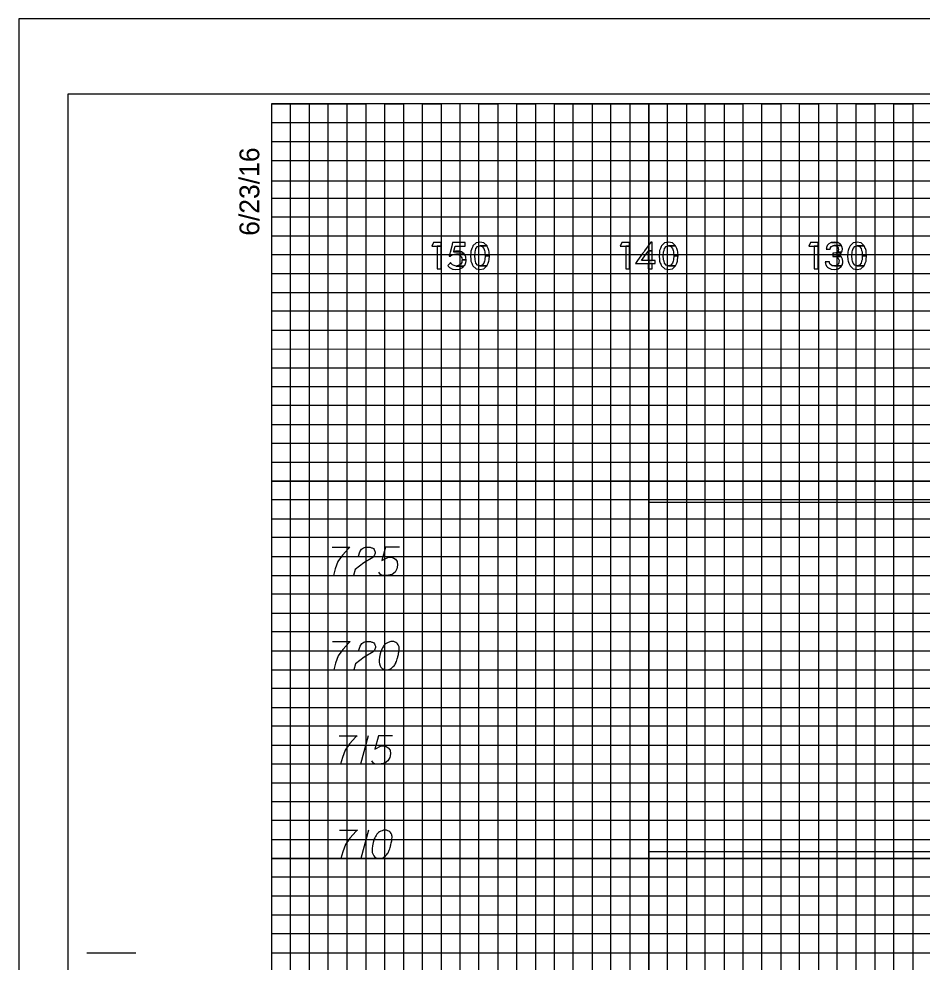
# Model space of a CAD drawing. Extents: x -13 to 323, y -5 to 1431.
# Drawn here: x -13.4 to 34.5, y 824.5 to 874.5 of the extents above; entities that cross this region are included whole.
import ezdxf

# ---------------------------------------------------------------- set-up
doc = ezdxf.new("R2010")
doc.units = 0
for name, color, linetype in [('Prop XS Elevation Labels', 7, 'Continuous'), ('Prop XS Offset Labels', 7, 'Continuous'), ('Scratch_Level_3', 7, 'Continuous'), ('Sheet Cross Section CELL', 7, 'Continuous'), ('Sheet Cross Section Grid Major CELL', 7, 'Continuous'), ('Sheet Cross Section Grid Middle CELL', 7, 'Continuous'), ('Sheet Cross Section Grid Minor 1 CELL', 7, 'Continuous'), ('Sheet Cross Section Grid Minor 2 CELL', 7, 'Continuous'), ('Sheet Cutting Line CELL', 7, 'Continuous'), ('Sheet DOT Grid CELL', 7, 'Continuous'), ('Sheet Plot Border Inside CELL', 7, 'Continuous'), ('Sheet Plot Border Outside CELL', 7, 'Continuous')]:
    doc.layers.add(name, color=color, linetype=linetype)

msp = doc.modelspace()

# ---------------------------------------------------------------- linework, layer by layer
at = {"layer": 'Prop XS Elevation Labels'}
for p, q in [((5.124, 836.5), (4.723, 835)), ((5.142, 831.5), (4.74, 830))]:
    msp.add_line(p, q, dxfattribs=at)
for points in [[(3.211, 846.5), (4.155, 846.5), (4.096, 846.441), (3.754, 846.075), (3.518, 845.744), (3.376, 845.354), (3.281, 845)], [(4.616, 846.028), (4.675, 846.252), (4.77, 846.394), (4.876, 846.453), (4.982, 846.488), (5.065, 846.5), (5.124, 846.5), (5.23, 846.488), (5.301, 846.465), (5.337, 846.453), (5.408, 846.417), (5.443, 846.37), (5.467, 846.323), (5.478, 846.287), (5.49, 846.24), (5.49, 846.181), (5.478, 846.122), (5.467, 846.087), (5.443, 846.039), (5.408, 845.992), (5.372, 845.957), (4.888, 845.661), (4.427, 845.319), (4.345, 845), (5.419, 845)], [(6.789, 846.5), (6.045, 846.5), (5.856, 845.791), (6.199, 845.969), (6.4, 845.969), (6.565, 845.862), (6.66, 845.744), (6.683, 845.543), (6.648, 845.342), (6.553, 845.177), (6.388, 845.047), (6.104, 845), (5.892, 845), (5.785, 845.047), (5.691, 845.177)], [(3.228, 841.5), (4.173, 841.5), (4.114, 841.441), (3.772, 841.075), (3.535, 840.744), (3.394, 840.354), (3.299, 840)], [(4.634, 841.028), (4.693, 841.252), (4.787, 841.394), (4.894, 841.453), (5, 841.488), (5.083, 841.5), (5.142, 841.5), (5.248, 841.488), (5.319, 841.465), (5.354, 841.453), (5.425, 841.417), (5.461, 841.37), (5.484, 841.323), (5.496, 841.287), (5.508, 841.24), (5.508, 841.181), (5.496, 841.122), (5.484, 841.087), (5.461, 841.039), (5.425, 840.992), (5.39, 840.957), (4.906, 840.661), (4.445, 840.319), (4.362, 840), (5.437, 840)], [(6.417, 841.5), (6.394, 841.5), (6.323, 841.488), (6.276, 841.476), (6.24, 841.465), (6.181, 841.441), (6.11, 841.406), (6.051, 841.37), (5.992, 841.323), (5.957, 841.276), (5.921, 841.217), (5.886, 841.158), (5.85, 841.087), (5.827, 841.039), (5.803, 840.969), (5.768, 840.85), (5.732, 840.673), (5.709, 840.531), (5.709, 840.402), (5.721, 840.307), (5.768, 840.201), (5.803, 840.142), (5.862, 840.071), (5.933, 840.024), (5.968, 840.012), (6.039, 840), (6.098, 840), (6.193, 840.012), (6.276, 840.035), (6.335, 840.071), (6.417, 840.13), (6.453, 840.165), (6.5, 840.213), (6.535, 840.26), (6.559, 840.295), (6.583, 840.354), (6.594, 840.378), (6.618, 840.437), (6.642, 840.508), (6.665, 840.579), (6.677, 840.626), (6.689, 840.661), (6.701, 840.709), (6.724, 840.815), (6.736, 840.874), (6.748, 840.933), (6.76, 841.016), (6.772, 841.122), (6.772, 841.158), (6.76, 841.205), (6.748, 841.252), (6.713, 841.323), (6.677, 841.37), (6.642, 841.406), (6.594, 841.441), (6.547, 841.465), (6.512, 841.476), (6.476, 841.488), (6.417, 841.5)], [(3.589, 836.5), (4.533, 836.5), (4.474, 836.441), (4.132, 836.075), (3.896, 835.744), (3.754, 835.354), (3.659, 835)], [(6.411, 836.5), (5.667, 836.5), (5.478, 835.791), (5.821, 835.969), (6.022, 835.969), (6.187, 835.862), (6.282, 835.744), (6.305, 835.543), (6.27, 835.342), (6.175, 835.177), (6.01, 835.047), (5.726, 835), (5.514, 835), (5.408, 835.047), (5.313, 835.177)], [(3.606, 831.5), (4.551, 831.5), (4.492, 831.441), (4.149, 831.075), (3.913, 830.744), (3.772, 830.354), (3.677, 830)], [(6.039, 831.5), (6.016, 831.5), (5.945, 831.488), (5.898, 831.476), (5.862, 831.465), (5.803, 831.441), (5.732, 831.406), (5.673, 831.37), (5.614, 831.323), (5.579, 831.276), (5.543, 831.217), (5.508, 831.158), (5.472, 831.087), (5.449, 831.039), (5.425, 830.969), (5.39, 830.85), (5.354, 830.673), (5.331, 830.531), (5.331, 830.402), (5.343, 830.307), (5.39, 830.201), (5.425, 830.142), (5.484, 830.071), (5.555, 830.024), (5.591, 830.012), (5.661, 830), (5.72, 830), (5.815, 830.012), (5.898, 830.035), (5.957, 830.071), (6.039, 830.13), (6.075, 830.165), (6.122, 830.213), (6.157, 830.26), (6.181, 830.295), (6.205, 830.354), (6.217, 830.378), (6.24, 830.437), (6.264, 830.508), (6.287, 830.579), (6.299, 830.626), (6.311, 830.661), (6.323, 830.709), (6.347, 830.815), (6.358, 830.874), (6.37, 830.933), (6.382, 831.016), (6.394, 831.122), (6.394, 831.158), (6.382, 831.205), (6.37, 831.252), (6.335, 831.323), (6.299, 831.37), (6.264, 831.406), (6.217, 831.441), (6.169, 831.465), (6.134, 831.476), (6.098, 831.488), (6.039, 831.5)]]:
    msp.add_lwpolyline(points, dxfattribs=at)
at = {"layer": 'Prop XS Offset Labels'}
for points in [[(8.581, 862.641), (8.492, 862.459), (8.99, 862.459), (8.99, 862.641)], [(9.427, 861.94), (9.424, 861.928), (9.495, 861.928), (9.508, 861.94), (9.524, 861.954), (9.595, 861.997), (9.627, 862.007), (9.697, 862.029), (9.811, 862.035), (10.219, 862.035), (10.211, 862.05), (10.076, 862.145), (9.655, 862.145), (9.658, 862.158), (9.658, 862.158), (9.663, 862.178), (9.738, 862.456), (10.263, 862.456), (10.263, 862.641), (9.6, 862.641), (9.554, 862.456), (9.486, 862.178), (9.481, 862.158), (9.478, 862.145), (9.454, 862.05), (9.451, 862.035), (9.449, 862.029), (9.444, 862.007), (9.441, 861.997), (9.431, 861.954)], [(10.851, 861.255), (11.051, 861.214), (11.245, 861.255), (11.256, 861.257), (11.422, 861.409), (11.047, 861.409), (11.038, 861.411), (11.033, 861.413), (10.928, 861.442), (10.841, 861.555), (10.841, 861.556), (10.841, 861.556), (10.813, 861.657), (10.813, 861.659), (10.793, 861.732), (10.792, 861.736), (10.774, 861.939), (10.774, 861.941), (10.774, 861.943), (10.792, 862.145), (10.812, 862.222), (10.813, 862.224), (10.839, 862.322), (10.84, 862.325), (10.928, 862.44), (11.041, 862.469), (11.045, 862.47), (11.055, 862.473), (11.425, 862.473), (11.262, 862.622), (11.254, 862.624), (11.053, 862.668), (11.053, 862.668), (10.845, 862.624), (10.843, 862.622), (10.681, 862.473), (10.678, 862.47), (10.678, 862.469), (10.665, 862.44), (10.618, 862.325), (10.617, 862.322), (10.577, 862.224), (10.576, 862.222), (10.568, 862.145), (10.547, 861.943), (10.547, 861.941), (10.547, 861.939), (10.567, 861.736), (10.568, 861.732), (10.575, 861.659), (10.575, 861.657), (10.616, 861.556), (10.617, 861.555), (10.663, 861.442), (10.675, 861.413), (10.676, 861.411), (10.679, 861.409), (10.848, 861.257)], [(18.581, 862.641), (18.492, 862.459), (18.99, 862.459), (18.99, 862.641)], [(19.411, 861.693), (19.297, 861.534), (20.35, 861.534), (20.35, 861.693), (19.618, 861.693), (19.878, 862.059), (19.935, 862.139), (19.977, 862.199), (20.179, 862.199), (20.179, 862.668), (20.114, 862.668), (19.775, 862.199), (19.733, 862.139), (19.675, 862.059)], [(20.851, 861.255), (21.051, 861.214), (21.245, 861.255), (21.256, 861.257), (21.422, 861.409), (21.047, 861.409), (21.038, 861.411), (21.033, 861.413), (20.928, 861.442), (20.841, 861.555), (20.841, 861.556), (20.841, 861.556), (20.813, 861.657), (20.813, 861.659), (20.793, 861.732), (20.792, 861.736), (20.774, 861.939), (20.774, 861.941), (20.774, 861.943), (20.792, 862.145), (20.812, 862.222), (20.813, 862.224), (20.839, 862.322), (20.84, 862.325), (20.928, 862.44), (21.041, 862.469), (21.045, 862.47), (21.055, 862.473), (21.425, 862.473), (21.262, 862.622), (21.254, 862.624), (21.053, 862.668), (21.053, 862.668), (20.845, 862.624), (20.843, 862.622), (20.681, 862.473), (20.678, 862.47), (20.678, 862.469), (20.665, 862.44), (20.618, 862.325), (20.617, 862.322), (20.577, 862.224), (20.576, 862.222), (20.568, 862.145), (20.547, 861.943), (20.547, 861.941), (20.547, 861.939), (20.567, 861.736), (20.567, 861.732), (20.575, 861.659), (20.575, 861.657), (20.616, 861.556), (20.617, 861.555), (20.663, 861.442), (20.675, 861.413), (20.676, 861.411), (20.679, 861.409), (20.848, 861.257)], [(28.581, 862.641), (28.492, 862.459), (28.99, 862.459), (28.99, 862.641)], [(29.42, 862.315), (29.418, 862.297), (29.626, 862.297), (29.627, 862.315), (29.639, 862.365), (29.64, 862.372), (29.641, 862.373), (29.683, 862.433), (29.688, 862.436), (29.696, 862.44), (29.748, 862.47), (29.785, 862.476), (29.795, 862.478), (29.835, 862.485), (30.217, 862.485), (30.165, 862.561), (30.129, 862.582), (30.128, 862.582), (30.023, 862.644), (29.982, 862.65), (29.69, 862.65), (29.678, 862.644), (29.553, 862.582), (29.536, 862.561), (29.471, 862.485), (29.466, 862.478), (29.465, 862.476), (29.463, 862.47), (29.452, 862.44), (29.45, 862.436), (29.449, 862.433), (29.428, 862.373), (29.427, 862.372), (29.425, 862.365)], [(29.853, 862.668), (29.69, 862.65), (29.982, 862.65)], [(30.851, 861.255), (31.051, 861.214), (31.245, 861.255), (31.256, 861.257), (31.422, 861.409), (31.047, 861.409), (31.038, 861.411), (31.033, 861.413), (30.928, 861.442), (30.841, 861.555), (30.841, 861.556), (30.841, 861.556), (30.813, 861.657), (30.813, 861.659), (30.793, 861.732), (30.792, 861.736), (30.774, 861.939), (30.774, 861.941), (30.774, 861.943), (30.792, 862.145), (30.812, 862.222), (30.813, 862.224), (30.839, 862.322), (30.84, 862.325), (30.928, 862.44), (31.041, 862.469), (31.045, 862.47), (31.055, 862.473), (31.425, 862.473), (31.262, 862.622), (31.254, 862.624), (31.053, 862.668), (31.053, 862.668), (30.845, 862.624), (30.843, 862.622), (30.681, 862.473), (30.678, 862.47), (30.678, 862.469), (30.665, 862.44), (30.618, 862.325), (30.617, 862.322), (30.577, 862.224), (30.576, 862.222), (30.568, 862.145), (30.547, 861.943), (30.547, 861.941), (30.547, 861.939), (30.567, 861.736), (30.567, 861.732), (30.575, 861.659), (30.575, 861.657), (30.616, 861.556), (30.617, 861.555), (30.663, 861.442), (30.675, 861.413), (30.676, 861.411), (30.679, 861.409), (30.848, 861.257)], [(8.781, 862.459), (8.781, 861.25), (8.99, 861.25), (8.99, 862.459)], [(9.692, 862.158), (9.655, 862.145), (10.076, 862.145), (10.058, 862.158), (9.961, 862.178), (9.75, 862.178)], [(9.888, 862.192), (9.75, 862.178), (9.96, 862.178), (9.888, 862.192)], [(10.083, 861.841), (10.105, 861.721), (10.318, 861.721), (10.307, 861.841), (10.307, 861.841), (10.303, 861.881), (10.284, 861.916), (10.278, 861.928), (10.271, 861.94), (10.263, 861.954), (10.24, 861.997), (10.235, 862.007), (10.223, 862.029), (10.219, 862.035), (9.811, 862.035), (9.838, 862.029), (9.928, 862.007), (9.943, 861.997), (10.003, 861.954), (10.024, 861.94), (10.031, 861.928), (10.038, 861.916), (10.059, 861.881)], [(11.312, 862.145), (11.328, 861.943), (11.555, 861.943), (11.536, 862.145), (11.528, 862.222), (11.527, 862.224), (11.527, 862.224), (11.488, 862.322), (11.488, 862.322), (11.487, 862.325), (11.441, 862.44), (11.44, 862.44), (11.429, 862.469), (11.428, 862.47), (11.425, 862.473), (11.055, 862.473), (11.065, 862.47), (11.068, 862.469), (11.175, 862.44), (11.262, 862.325), (11.265, 862.322), (11.291, 862.224), (11.291, 862.222)], [(18.781, 862.459), (18.781, 861.25), (18.99, 861.25), (18.99, 862.459)], [(19.97, 862.059), (19.97, 861.693), (20.179, 861.693), (20.179, 862.059), (20.179, 862.139), (20.179, 862.199), (19.977, 862.199), (19.973, 862.139)], [(21.312, 862.145), (21.328, 861.943), (21.555, 861.943), (21.536, 862.145), (21.528, 862.222), (21.527, 862.224), (21.527, 862.224), (21.488, 862.322), (21.488, 862.322), (21.487, 862.325), (21.441, 862.44), (21.44, 862.44), (21.429, 862.469), (21.428, 862.47), (21.425, 862.473), (21.055, 862.473), (21.065, 862.47), (21.068, 862.469), (21.175, 862.44), (21.262, 862.325), (21.265, 862.322), (21.291, 862.224), (21.291, 862.222)], [(28.781, 862.459), (28.781, 861.25), (28.99, 861.25), (28.99, 862.459)], [(29.765, 861.956), (29.765, 861.9), (30.194, 861.9), (30.119, 861.956), (30.029, 861.983), (30.095, 862), (30.181, 862.053), (30.2, 862.084), (30.201, 862.085), (30.207, 862.095), (29.915, 862.095), (29.83, 862.085), (29.765, 862.084), (29.765, 862.053), (29.765, 862), (29.765, 861.983)], [(30.007, 862.155), (29.988, 862.131), (30.23, 862.131), (30.246, 862.155), (30.254, 862.201), (30.271, 862.289), (30.272, 862.295), (30.272, 862.297), (30.269, 862.315), (30.26, 862.365), (30.259, 862.372), (30.259, 862.373), (30.259, 862.373), (30.249, 862.433), (30.248, 862.436), (30.248, 862.44), (30.227, 862.47), (30.223, 862.476), (30.222, 862.478), (30.217, 862.485), (29.835, 862.485), (29.901, 862.478), (29.919, 862.476), (29.931, 862.47), (29.986, 862.44), (29.995, 862.436), (29.997, 862.433), (30.04, 862.373), (30.04, 862.372), (30.042, 862.365), (30.051, 862.315), (30.054, 862.297), (30.055, 862.295), (30.056, 862.289), (30.041, 862.201)], [(29.988, 862.131), (29.915, 862.095), (30.207, 862.095), (30.23, 862.131)], [(31.312, 862.145), (31.328, 861.943), (31.555, 861.943), (31.536, 862.145), (31.528, 862.222), (31.527, 862.224), (31.527, 862.224), (31.488, 862.322), (31.488, 862.322), (31.487, 862.325), (31.441, 862.44), (31.44, 862.44), (31.429, 862.469), (31.428, 862.47), (31.425, 862.473), (31.055, 862.473), (31.065, 862.47), (31.068, 862.469), (31.175, 862.44), (31.262, 862.325), (31.265, 862.322), (31.291, 862.224), (31.291, 862.222)], [(9.626, 861.233), (9.762, 861.214), (9.959, 861.233), (9.968, 861.237), (10.091, 861.297), (10.091, 861.297), (10.141, 861.321), (10.185, 861.375), (10.204, 861.399), (9.793, 861.399), (9.683, 861.418), (9.682, 861.419), (9.679, 861.42), (9.596, 861.466), (9.586, 861.477), (9.58, 861.483), (9.58, 861.483), (9.529, 861.535), (9.497, 861.585), (9.497, 861.585), (9.451, 861.535), (9.404, 861.483), (9.399, 861.477), (9.39, 861.466), (9.348, 861.42), (9.347, 861.419), (9.348, 861.418), (9.363, 861.399), (9.382, 861.375), (9.445, 861.321), (9.474, 861.297), (9.598, 861.237)], [(9.424, 861.928), (9.482, 861.916), (9.495, 861.928)], [(9.9, 861.418), (9.793, 861.399), (10.204, 861.399), (10.22, 861.418), (10.221, 861.419), (10.222, 861.42), (10.222, 861.42), (10.259, 861.466), (10.268, 861.477), (10.27, 861.483), (10.284, 861.535), (10.299, 861.59), (10.322, 861.674), (10.318, 861.721), (10.105, 861.721), (10.097, 861.674), (10.082, 861.59), (10.047, 861.535), (10.014, 861.483), (10.004, 861.477), (9.987, 861.466), (9.913, 861.42), (9.905, 861.419)], [(11.058, 861.411), (11.047, 861.409), (11.422, 861.409), (11.425, 861.411), (11.426, 861.413), (11.438, 861.442), (11.485, 861.555), (11.485, 861.556), (11.527, 861.657), (11.528, 861.659), (11.535, 861.732), (11.535, 861.736), (11.555, 861.939), (11.556, 861.941), (11.555, 861.943), (11.328, 861.943), (11.328, 861.941), (11.328, 861.939), (11.312, 861.736), (11.312, 861.732), (11.292, 861.659), (11.291, 861.657), (11.264, 861.556), (11.263, 861.555), (11.175, 861.442), (11.063, 861.413)], [(19.97, 861.534), (19.97, 861.25), (20.179, 861.25), (20.179, 861.534)], [(21.058, 861.411), (21.047, 861.409), (21.422, 861.409), (21.425, 861.411), (21.426, 861.413), (21.438, 861.442), (21.485, 861.555), (21.485, 861.556), (21.527, 861.657), (21.528, 861.659), (21.535, 861.732), (21.535, 861.736), (21.555, 861.939), (21.556, 861.941), (21.555, 861.943), (21.328, 861.943), (21.328, 861.941), (21.328, 861.939), (21.312, 861.736), (21.312, 861.732), (21.292, 861.659), (21.291, 861.657), (21.264, 861.556), (21.263, 861.555), (21.175, 861.442), (21.063, 861.413)], [(29.677, 861.229), (29.854, 861.214), (29.936, 861.229), (30.042, 861.248), (30.123, 861.297), (30.187, 861.336), (30.228, 861.399), (30.229, 861.401), (29.849, 861.401), (29.72, 861.416), (29.711, 861.423), (29.639, 861.471), (29.628, 861.479), (29.626, 861.482), (29.608, 861.516), (29.584, 861.562), (29.584, 861.567), (29.58, 861.62), (29.58, 861.625), (29.361, 861.625), (29.362, 861.62), (29.369, 861.567), (29.37, 861.562), (29.377, 861.516), (29.391, 861.482), (29.392, 861.479), (29.395, 861.471), (29.415, 861.423), (29.418, 861.416), (29.425, 861.401), (29.426, 861.399), (29.49, 861.336), (29.53, 861.297), (29.635, 861.248)], [(29.925, 861.416), (29.849, 861.401), (30.229, 861.401), (30.239, 861.416), (30.243, 861.423), (30.243, 861.423), (30.275, 861.471), (30.277, 861.479), (30.277, 861.482), (30.283, 861.516), (30.292, 861.562), (30.293, 861.567), (30.303, 861.62), (30.297, 861.662), (30.285, 861.751), (30.283, 861.763), (30.25, 861.826), (30.223, 861.877), (30.222, 861.88), (30.197, 861.898), (30.194, 861.9), (29.81, 861.9), (29.878, 861.898), (29.951, 861.88), (29.963, 861.877), (30.033, 861.826), (30.07, 861.763), (30.077, 861.751), (30.092, 861.662), (30.088, 861.62), (30.083, 861.567), (30.08, 861.562), (30.057, 861.516), (30.039, 861.482), (30.035, 861.479), (30.025, 861.471), (29.957, 861.423)], [(31.058, 861.411), (31.047, 861.409), (31.422, 861.409), (31.425, 861.411), (31.426, 861.413), (31.438, 861.442), (31.485, 861.555), (31.485, 861.556), (31.527, 861.657), (31.528, 861.659), (31.535, 861.732), (31.535, 861.736), (31.555, 861.939), (31.556, 861.941), (31.555, 861.943), (31.328, 861.943), (31.328, 861.941), (31.328, 861.939), (31.312, 861.736), (31.312, 861.732), (31.292, 861.659), (31.291, 861.657), (31.264, 861.556), (31.263, 861.555), (31.175, 861.442), (31.063, 861.413)]]:
    msp.add_lwpolyline(points, close=True, dxfattribs=at)
at = {"layer": 'Scratch_Level_3'}
msp.add_lwpolyline([(20, 848.886), (300, 848.886), (300, 830.355), (20, 830.355)], close=True, dxfattribs=at)
at = {"layer": 'Sheet Cross Section CELL'}
for p, q in [((-9.8, 825), (-7.3, 825)), ((-9.7, 825), (-7.2, 825))]:
    msp.add_line(p, q, dxfattribs=at)
msp.add_lwpolyline([(320, 870), (0, 870), (0, 660), (320, 660)], close=True, dxfattribs=at)
at = {"layer": 'Sheet Cross Section Grid Major CELL'}
for p, q in [((10, 870), (0, 870)), ((10, 660), (10, 870)), ((30, 870), (20, 870)), ((20, 870), (20, 660)), ((30, 660), (30, 870))]:
    msp.add_line(p, q, dxfattribs=at)
for points in [[(0, 860), (320, 860), (320, 850), (0, 850)], [(0, 840), (320, 840), (320, 830), (0, 830)]]:
    msp.add_lwpolyline(points, dxfattribs=at)
at = {"layer": 'Sheet Cross Section Grid Middle CELL'}
for points in [[(0, 870), (5, 870), (5, 660)], [(15, 660), (15, 870), (25, 870), (25, 660)], [(0, 865), (275, 865)], [(0, 845), (320, 845), (320, 855), (0, 855)], [(0, 825), (320, 825), (320, 835), (0, 835)]]:
    msp.add_lwpolyline(points, dxfattribs=at)
at = {"layer": 'Sheet Cross Section Grid Minor 1 CELL'}
for p, q in [((0, 869), (260, 869)), ((260, 867.98), (0, 867.98)), ((0, 867.98), (0, 867)), ((0, 867), (260, 867)), ((260, 865.89), (0, 865.89)), ((0, 865.89), (0, 864)), ((0, 864), (320, 864))]:
    msp.add_line(p, q, dxfattribs=at)
for points in [[(0, 863), (270, 863), (320, 863), (320, 862), (0, 862)], [(0, 861), (320, 861), (320, 859), (0, 859)], [(0, 858), (320, 858), (320, 857), (0, 856.98)], [(0, 856), (320, 856), (320, 854), (0, 854)], [(0, 853), (320, 853), (320, 852), (0, 852)], [(0, 851), (320, 851), (320, 849), (0, 849)], [(0, 848), (320, 848), (320, 847), (0, 847)], [(0, 846), (320, 846), (320, 844), (0, 844)], [(0, 843), (320, 843), (320, 842), (0, 842)], [(0, 841), (320, 841), (320, 839), (0, 839)], [(0, 838), (320, 838), (320, 837), (0, 837)], [(0, 836), (320, 836), (320, 833.95), (320, 833), (320, 832), (0, 832)], [(0, 834), (320, 834), (320, 833), (0, 833)], [(0, 831), (320, 831), (320, 829), (0, 829.03)], [(0, 829.03), (320, 829), (320, 828), (0, 828)], [(0, 827), (320, 827), (320, 826), (0, 826)]]:
    msp.add_lwpolyline(points, dxfattribs=at)
at = {"layer": 'Sheet Cross Section Grid Minor 2 CELL'}
for points in [[(0, 660), (1, 660), (1, 870), (2, 870), (2, 660)], [(2, 660), (3, 660), (3, 870), (4, 870), (4, 660)], [(5, 660), (6, 660), (6, 870), (7, 870), (7, 660)], [(7, 660), (8, 660), (8, 870), (9, 870), (9, 660)], [(10, 660), (11, 660), (11, 870), (12, 870), (12, 660)], [(12, 660), (13, 660), (13, 870), (14, 870), (14, 660)], [(15, 660), (16, 660), (16, 870), (17, 870), (17, 660)], [(17, 660), (18, 660), (18, 870), (19, 870), (19, 660)], [(20, 660), (21, 660), (21, 870), (22, 870), (22, 660)], [(22, 660), (23, 660), (23, 870), (24, 870), (24, 660)], [(25, 660), (26, 660), (26, 870), (27, 870), (27, 660)], [(27, 660), (28, 660), (28, 870), (29, 870), (29, 660)], [(30, 660), (31, 660), (31, 870), (32, 870), (32, 660)], [(32, 660), (33, 660), (33, 870), (34, 870), (34, 660)]]:
    msp.add_lwpolyline(points, dxfattribs=at)
at = {"layer": 'Sheet Cutting Line CELL'}
for p, q in [((323.3, 874.5), (-13.4, 874.5)), ((-13.4, 874.5), (-13.4, 655.5))]:
    msp.add_line(p, q, dxfattribs=at)
at = {"layer": 'Sheet DOT Grid CELL'}
for p, q in [((10, 660), (10, 870)), ((20, 660), (20, 870)), ((30, 660), (30, 870)), ((0, 860), (320, 860)), ((0, 850), (320, 850)), ((0, 840), (320, 840)), ((0, 830), (320, 830))]:
    msp.add_line(p, q, dxfattribs=at)
at = {"layer": 'Sheet Plot Border Inside CELL'}
msp.add_lwpolyline([(-10.8, 659.5), (322.4, 659.5), (322.4, 870.5), (-10.8, 870.5)], close=True, dxfattribs=at)
at = {"layer": 'Sheet Plot Border Outside CELL'}
msp.add_lwpolyline([(-13.4, 655.5), (323.3, 655.5), (323.3, 874.5), (-13.4, 874.5)], close=True, dxfattribs=at)

# ---------------------------------------------------------------- texts
at = {"layer": 'Sheet Cross Section CELL'}
msp.add_text('6/23/16', height=1.05, rotation=90, dxfattribs=at).set_placement((-0.65, 863))

doc.saveas('drawing.dxf')
